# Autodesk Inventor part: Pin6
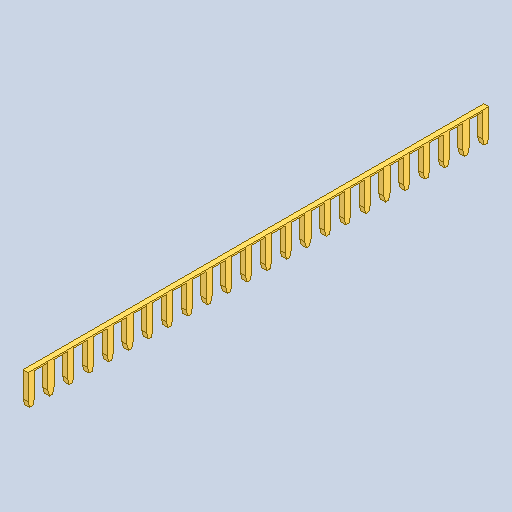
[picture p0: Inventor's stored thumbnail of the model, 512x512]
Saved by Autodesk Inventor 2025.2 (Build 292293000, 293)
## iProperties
Created: 2025-04
Part Number: Pin6
Material: Generic
Description: PART--DESC
Document SubType Name: Modeling
Designer: BennF
Density: 1 g/cm^3
Appearance: Default
Author: BennF
Revision Number: NONE
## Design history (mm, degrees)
feature "Solid13"
body "Solid1"
